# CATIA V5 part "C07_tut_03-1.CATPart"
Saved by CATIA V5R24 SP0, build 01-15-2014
Part number: Part1
Bounding box of the stored display mesh (mm): x 0 to 108, y -53 to 53, z -53 to 53
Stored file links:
  D:\KAVITA\CATIA V5-6R2014 Project_ Kavita\CATIA V5-6R2014_partfiles\Tutorials\c07_catia_v5-6r2014_tut\c07tut3.CATPart
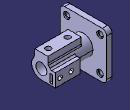
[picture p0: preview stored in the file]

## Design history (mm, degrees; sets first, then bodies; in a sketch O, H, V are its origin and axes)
Body1 (main body)
  Sketch1 on yz-plane, origin (0, 0, 0), H (0, 1, 0), V (0, 0, 1)
    line L1 (53, 43) -> (53, -43)
    line L2 (43, -53) -> (-43, -53)
    line L3 (-53, -43) -> (-53, 43)
    line L4 (-43, 53) -> (43, 53)
    point P1 (53, 53)
    point P2 (53, -53)
    point P3 (-53, -53)
    arc A1 centre (43, 43) radius 10 from (53, 43) to (43, 53) ccw
    arc A2 centre (43, -43) radius 10 from (53, -43) to (43, -53) cw
    arc A3 centre (-43, -43) radius 10 from (-43, -53) to (-53, -43) cw
    arc A4 centre (-43, 43) radius 10 from (-53, 43) to (-43, 53) cw
    distance P1 P2 = 106
    radius A1 = 10
    distance P2 P3 = 106
    radius A2 = 10
    radius A3 = 10
    radius A4 = 10
    vertical: L1 V, L3 V
    horizontal: L2 H, L4 H
    equidistance: L1 L3 O, L2 L4 O
    coincidence: L1 P1, L4 P1, L1 P2, L2 P2, L2 P3, L3 P3
    tangency: A1 L1, A1 L4, A2 L1, A2 L2, A3 L2, A3 L3, A4 L3, A4 L4
  Pad1: profile Sketch1, direction (1, 0, 0), length 12
  Sketch2 on face of Pad1, origin (12, 0, 0), H (0, 1, 0), V (0, 0, 1)
    circle A1 centre (0, 0) radius 22
    radius A1 = 22
  Pad2: profile Sketch2, direction (1, 0, 0), length 96
  Sketch3 on face of Pad2, origin (108, 0, 0), H (0, 1, 0), V (0, 0, 1)
    point P1 (-15, 16.0935)
    line L1 (-15, 16.0935) -> (-15, 32)
    line L2 (-15, 32) -> (15, 32)
    line L3 (15, 32) -> (15, 16.0935)
    point P4 (15, 16.0935)
    axis line L4 (0, 0) -> (0, 32)
    point P5 (0, 32)
    reference projected circle E1 centre (0, 0) radius 22 from edge [face of Pad2 | face of Pad2]
    reference projected circle E2 centre (0, 0) radius 22 from edge [face of Pad2 | face of Pad2]
    projected circle E3 centre (0, 0) radius 22 from edge [face of Pad2 | face of Pad2]
    projected arc E4 centre (0, 0) radius 22 from (15, 16.0935) to (-15, 16.0935) ccw from edge [face of Pad2 | face of Pad2]
    length L2 = 30
    distance H L2 = 32
    vertical: L1 V, L3 V, L4 V
    horizontal: L2 H
    midpoint: P5 L2
    coincidence: P4 E1, P1 E2
  Pad3: profile Sketch3, direction (-1, 0, 0), length 76
  Sketch4 on face of Pad2, origin (108, 0, 0), H (0, 1, 0), V (0, 0, 1)
    point P1 (0, -22)
    line L1 (0, -22) -> (32, -22)
    line L2 (32, -22) -> (32, 8)
    line L3 (32, 8) -> (20.4939, 8)
    point P4 (20.4939, 8)
    reference projected circle E1 centre (0, 0) radius 22 from edge of Pad2
    reference projected circle E2 centre (0, 0) radius 22 from edge [face of Pad2 | face of Pad2]
    reference projected circle E3 centre (0, 0) radius 22 from edge [face of Pad2 | face of Pad2]
    projected arc E4 centre (0, 0) radius 22 from (-15, 16.0935) to (15, 16.0935) ccw from edge of Pad3
    projected arc E5 centre (0, 0) radius 22 from (0, -22) to (20.4939, 8) ccw from edge of Pad3
    length L2 = 30
    distance V L2 = 32
    coincidence: P1 V, P4 E1, P1 E2
    horizontal: L1 H, L3 H
    vertical: L2 V
    tangency: L1 E3
  Pad4: profile Sketch4, direction (-1, 0, 0), length 57
  Sketch5 on face of Pad2, origin (108, 0, 0), H (0, 1, 0), V (0, 0, 1)
    line L1 (19, 1) -> (25, 1)
    line L2 (25, 1) -> (25, -18)
    line L3 (25, -18) -> (19, -18)
    line L4 (19, -18) -> (19, 1)
    reference projected line E1 (53, -43) -> (53, 43) from edge [face of Pad1 | face of Pad1]
    reference projected line E2 (-43, -53) -> (43, -53) from edge [face of Pad1 | face of Pad1]
    length L3 = 6
    length L2 = 19
    distance L4 E1 = 34
    distance L3 E2 = 35
    horizontal: L1 H, L3 H
    vertical: L2 V, L4 V
  Pocket1: profile Sketch5, direction (-1, 0, 0), length 50
  Sketch6 on face of Pad2, origin (108, 0, 0), H (0, 1, 0), V (0, 0, 1)
    point P1 (0, 0)
    coincidence: P1 O
  Hole1: placed by Sketch6, at (108, 0, 0) direction (-1, 0, 0), diameter 25, depth 82, V-bottom angle 120
  Sketch7 on face of Pad3, origin (90.7325, -5.9449, 32), H (1, 0, 0), V (0, 1, 0)
    point P1 (1.2675, 5.9449)
    reference projected line E1 (17.2675, -9.0551) -> (-58.7325, -9.0551) from edge [face of Pad3 | face of Pad3]
    reference projected line E2 (17.2675, 20.9449) -> (17.2675, -9.0551) from edge [face of Pad3 | face of Pad3]
    distance P1 E1 = 15
    distance P1 E2 = 16
  Hole2: placed by Sketch7, at (92, 0, 32) direction (0, 0, -1), diameter 12, depth 33.0037, threaded, thread diameter 13.2, thread depth 10, pitch 1
  RectPattern1: of Hole2, direction 1 instances 2, spacing 44, along edge [face of Pad3 | face of Pad3]
  Sketch8 on face of Pad4, origin (86.2721, 32, -2.7131), H (1, 0, 0), V (0, 0, -1)
    point P1 (10.7279, 4.2869)
    reference projected line E1 (21.7279, 19.2869) -> (-35.2721, 19.2869) from edge [face of Pad4 | face of Pad4]
    reference projected line E2 (21.7279, 19.2869) -> (21.7279, -10.7131) from edge [face of Pad4 | face of Pad4]
    distance P1 E1 = 15
    distance E2 P1 = 11
  Hole3: placed by Sketch8, at (97, 32, -7) direction (0, -1, 0), diameter 10, through (limit type 6), threaded, thread diameter 11, thread depth 7.5, pitch 1
  RectPattern2: of Hole3, direction 1 instances 2, spacing 25, along edge [face of Pad4 | face of Pad4], direction 2 instances 2, spacing 76
  Sketch9 on face of Pad1, origin (12, -36.1764, 22.8739), H (0, 1, 0), V (0, 0, 1)
    point P1 (-1.8236, -60.8739)
    reference projected line E1 (-16.8236, 20.1261) -> (-16.8236, -65.8739) from edge [face of Pad1 | face of Pad1]
    reference projected line E2 (-6.8236, -75.8739) -> (79.1764, -75.8739) from edge [face of Pad1 | face of Pad1]
    distance P1 E1 = 15
    distance E2 P1 = 15
  Hole4: placed by Sketch9, at (12, -38, -38) direction (-1, 0, 0), diameter 10, through (limit type 3), counterbore diameter 15, counterbore depth 3
  RectPattern3: of Hole4, direction 1 instances 2, spacing 76, along edge [face of Pad1 | face of Pad1], direction 2 instances 2, spacing 76, along edge [face of Pad1 | face of Pad1] reversed
  Fillet1: radius 15, on edge [face of Pad3 | face of Pad2]
  Fillet2: radius 5, on edge [face of Pad2 | face of Pad3]; edge [face of Pad2 | face of Pad4]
